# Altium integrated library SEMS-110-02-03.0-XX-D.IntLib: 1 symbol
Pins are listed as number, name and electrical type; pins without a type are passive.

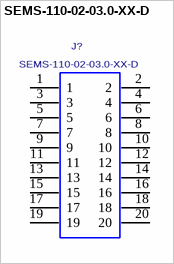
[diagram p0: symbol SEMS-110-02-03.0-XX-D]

## SEMS-110-02-03.0-XX-D
designator J?
0.8MM TIGER EYE MICRO SOCKET, 20 PINS.; MANUFACTURER: SAMTEC
footprint SEMS-110-02-03.0-XX-D
pins: 1, 2, 3, 4, 5, 6, 7, 8, 9, 10, 11, 12, 13, 14, 15, 16, 17, 18, 19, 20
